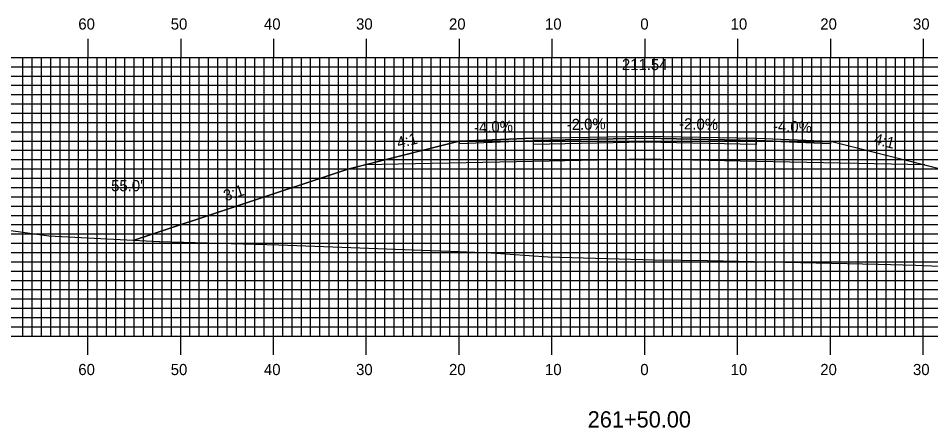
# Model space of a CAD drawing. Extents: x 1806258 to 1806601, y 442591 to 442811.
# Drawn here: x 1806356.2 to 1806454.5, y 442648.8 to 442692.9 of the extents above; entities that cross this region are included whole.
import ezdxf

# ---------------------------------------------------------------- set-up
doc = ezdxf.new("R2010")
doc.units = 0
for name, color, linetype in [('ANNOTATION', 7, 'Continuous'), ('D_Roadway_Centerline', 7, 'Continuous'), ('D_Roadway_Centerline_Text', 7, 'Continuous'), ('D_Roadway_Edge_Shoulder', 7, 'Continuous'), ('D_Roadway_Edge_TW', 7, 'Continuous'), ('D_Roadway_Pavement', 7, 'Continuous'), ('D_Roadway_SlopeLines', 7, 'Continuous'), ('D_Roadway_SubGrade', 7, 'Continuous'), ('D_Text_Standard', 7, 'Continuous'), ('H_V ANNOTATION', 7, 'Continuous'), ('MAJOR', 7, 'Continuous'), ('MINOR', 7, 'Continuous'), ('S_Roadway_Centerline', 7, 'Continuous')]:
    doc.layers.add(name, color=color, linetype=linetype)

msp = doc.modelspace()

# ---------------------------------------------------------------- linework, layer by layer
at = {"layer": 'D_Roadway_Centerline'}
msp.add_lwpolyline([(1806368.738, 442668.982), (1806391.733, 442676.646), (1806393.559, 442677.103), (1806403.733, 442679.646), (1806411.733, 442679.966), (1806423.733, 442680.206), (1806435.733, 442679.966), (1806443.733, 442679.646), (1806453.907, 442677.103), (1806455.733, 442676.646), (1806491.379, 442664.764)], dxfattribs=at)
at = {"layer": 'D_Roadway_Edge_Shoulder'}
for points in [[(1806411.733, 442679.966), (1806403.733, 442679.646), (1806403.733, 442679.396), (1806411.733, 442679.716)], [(1806435.733, 442679.966), (1806443.733, 442679.646), (1806443.733, 442679.396), (1806435.733, 442679.716)]]:
    msp.add_lwpolyline(points, close=True, dxfattribs=at)
at = {"layer": 'D_Roadway_Edge_TW'}
msp.add_lwpolyline([(1806411.733, 442679.716), (1806411.733, 442679.966), (1806423.733, 442680.206), (1806435.733, 442679.966), (1806435.733, 442679.716), (1806423.733, 442679.956)], close=True, dxfattribs=at)
at = {"layer": 'D_Roadway_Pavement'}
msp.add_lwpolyline([(1806411.733, 442679.3), (1806411.733, 442679.716), (1806423.733, 442679.956), (1806435.733, 442679.716), (1806435.733, 442679.3), (1806423.733, 442679.54)], close=True, dxfattribs=at)
at = {"layer": 'D_Roadway_SlopeLines'}
for points in [[(1806403.733, 442679.646), (1806391.733, 442676.646), (1806368.738, 442668.982)], [(1806443.733, 442679.646), (1806455.733, 442676.646), (1806491.379, 442664.764)]]:
    msp.add_lwpolyline(points, dxfattribs=at)
at = {"layer": 'D_Roadway_SubGrade'}
msp.add_lwpolyline([(1806411.733, 442677.466), (1806393.559, 442677.103), (1806403.733, 442679.646), (1806403.733, 442679.396), (1806411.733, 442679.716), (1806423.733, 442679.956), (1806435.733, 442679.716), (1806443.733, 442679.396), (1806443.733, 442679.646), (1806453.907, 442677.103), (1806435.733, 442677.466), (1806423.733, 442677.706)], close=True, dxfattribs=at)
at = {"layer": 'MAJOR'}
for p, q in [((1806363.733, 442690.669), (1806363.733, 442688.665)), ((1806373.733, 442690.669), (1806373.733, 442688.665)), ((1806383.733, 442690.669), (1806383.733, 442688.665)), ((1806393.733, 442690.669), (1806393.733, 442688.665)), ((1806403.733, 442690.669), (1806403.733, 442688.665)), ((1806413.733, 442690.669), (1806413.733, 442688.665)), ((1806423.733, 442690.669), (1806423.733, 442688.665)), ((1806433.733, 442690.669), (1806433.733, 442688.665)), ((1806443.733, 442690.669), (1806443.733, 442688.665)), ((1806453.733, 442690.669), (1806453.733, 442688.665)), ((1806283.733, 442688.665), (1806563.733, 442688.665)), ((1806283.733, 442688.665), (1806563.733, 442688.665)), ((1806363.733, 442658.665), (1806363.733, 442688.665)), ((1806373.733, 442658.665), (1806373.733, 442688.665)), ((1806383.733, 442658.665), (1806383.733, 442688.665)), ((1806393.733, 442658.665), (1806393.733, 442688.665)), ((1806403.733, 442658.665), (1806403.733, 442688.665)), ((1806413.733, 442658.665), (1806413.733, 442688.665)), ((1806423.733, 442658.665), (1806423.733, 442688.665)), ((1806433.733, 442658.665), (1806433.733, 442688.665)), ((1806443.733, 442658.665), (1806443.733, 442688.665)), ((1806453.733, 442658.665), (1806453.733, 442688.665)), ((1806283.733, 442683.665), (1806563.733, 442683.665)), ((1806283.733, 442678.665), (1806563.733, 442678.665)), ((1806283.733, 442673.665), (1806563.733, 442673.665)), ((1806283.733, 442668.665), (1806563.733, 442668.665)), ((1806283.733, 442663.665), (1806563.733, 442663.665)), ((1806283.733, 442658.665), (1806563.733, 442658.665)), ((1806283.733, 442658.665), (1806563.733, 442658.665)), ((1806363.733, 442656.661), (1806363.733, 442658.665)), ((1806373.733, 442656.661), (1806373.733, 442658.665)), ((1806383.733, 442656.661), (1806383.733, 442658.665)), ((1806393.733, 442656.661), (1806393.733, 442658.665)), ((1806403.733, 442656.661), (1806403.733, 442658.665)), ((1806413.733, 442656.661), (1806413.733, 442658.665)), ((1806423.733, 442656.661), (1806423.733, 442658.665)), ((1806433.733, 442656.661), (1806433.733, 442658.665)), ((1806443.733, 442656.661), (1806443.733, 442658.665)), ((1806453.733, 442656.661), (1806453.733, 442658.665))]:
    msp.add_line(p, q, dxfattribs=at)
at = {"layer": 'MINOR'}
for p, q in [((1806356.733, 442658.665), (1806356.733, 442688.665)), ((1806357.733, 442658.665), (1806357.733, 442688.665)), ((1806358.733, 442658.665), (1806358.733, 442688.665)), ((1806359.733, 442658.665), (1806359.733, 442688.665)), ((1806360.733, 442658.665), (1806360.733, 442688.665)), ((1806361.733, 442658.665), (1806361.733, 442688.665)), ((1806362.733, 442658.665), (1806362.733, 442688.665)), ((1806364.733, 442658.665), (1806364.733, 442688.665)), ((1806365.733, 442658.665), (1806365.733, 442688.665)), ((1806366.733, 442658.665), (1806366.733, 442688.665)), ((1806367.733, 442658.665), (1806367.733, 442688.665)), ((1806368.733, 442658.665), (1806368.733, 442688.665)), ((1806369.733, 442658.665), (1806369.733, 442688.665)), ((1806370.733, 442658.665), (1806370.733, 442688.665)), ((1806371.733, 442658.665), (1806371.733, 442688.665)), ((1806372.733, 442658.665), (1806372.733, 442688.665)), ((1806374.733, 442658.665), (1806374.733, 442688.665)), ((1806375.733, 442658.665), (1806375.733, 442688.665)), ((1806376.733, 442658.665), (1806376.733, 442688.665)), ((1806377.733, 442658.665), (1806377.733, 442688.665)), ((1806378.733, 442658.665), (1806378.733, 442688.665)), ((1806379.733, 442658.665), (1806379.733, 442688.665)), ((1806380.733, 442658.665), (1806380.733, 442688.665)), ((1806381.733, 442658.665), (1806381.733, 442688.665)), ((1806382.733, 442658.665), (1806382.733, 442688.665)), ((1806384.733, 442658.665), (1806384.733, 442688.665)), ((1806385.733, 442658.665), (1806385.733, 442688.665)), ((1806386.733, 442658.665), (1806386.733, 442688.665)), ((1806387.733, 442658.665), (1806387.733, 442688.665)), ((1806388.733, 442658.665), (1806388.733, 442688.665)), ((1806389.733, 442658.665), (1806389.733, 442688.665)), ((1806390.733, 442658.665), (1806390.733, 442688.665)), ((1806391.733, 442658.665), (1806391.733, 442688.665)), ((1806392.733, 442658.665), (1806392.733, 442688.665)), ((1806394.733, 442658.665), (1806394.733, 442688.665)), ((1806395.733, 442658.665), (1806395.733, 442688.665)), ((1806396.733, 442658.665), (1806396.733, 442688.665)), ((1806397.733, 442658.665), (1806397.733, 442688.665)), ((1806398.733, 442658.665), (1806398.733, 442688.665)), ((1806399.733, 442658.665), (1806399.733, 442688.665)), ((1806400.733, 442658.665), (1806400.733, 442688.665)), ((1806401.733, 442658.665), (1806401.733, 442688.665)), ((1806402.733, 442658.665), (1806402.733, 442688.665)), ((1806404.733, 442658.665), (1806404.733, 442688.665)), ((1806405.733, 442658.665), (1806405.733, 442688.665)), ((1806406.733, 442658.665), (1806406.733, 442688.665)), ((1806407.733, 442658.665), (1806407.733, 442688.665)), ((1806408.733, 442658.665), (1806408.733, 442688.665)), ((1806409.733, 442658.665), (1806409.733, 442688.665)), ((1806410.733, 442658.665), (1806410.733, 442688.665)), ((1806411.733, 442658.665), (1806411.733, 442688.665)), ((1806412.733, 442658.665), (1806412.733, 442688.665)), ((1806414.733, 442658.665), (1806414.733, 442688.665)), ((1806415.733, 442658.665), (1806415.733, 442688.665)), ((1806416.733, 442658.665), (1806416.733, 442688.665)), ((1806417.733, 442658.665), (1806417.733, 442688.665)), ((1806418.733, 442658.665), (1806418.733, 442688.665)), ((1806419.733, 442658.665), (1806419.733, 442688.665)), ((1806420.733, 442658.665), (1806420.733, 442688.665)), ((1806421.733, 442658.665), (1806421.733, 442688.665)), ((1806422.733, 442658.665), (1806422.733, 442688.665)), ((1806424.733, 442658.665), (1806424.733, 442688.665)), ((1806425.733, 442658.665), (1806425.733, 442688.665)), ((1806426.733, 442658.665), (1806426.733, 442688.665)), ((1806427.733, 442658.665), (1806427.733, 442688.665)), ((1806428.733, 442658.665), (1806428.733, 442688.665)), ((1806429.733, 442658.665), (1806429.733, 442688.665)), ((1806430.733, 442658.665), (1806430.733, 442688.665)), ((1806431.733, 442658.665), (1806431.733, 442688.665)), ((1806432.733, 442658.665), (1806432.733, 442688.665)), ((1806434.733, 442658.665), (1806434.733, 442688.665)), ((1806435.733, 442658.665), (1806435.733, 442688.665)), ((1806436.733, 442658.665), (1806436.733, 442688.665)), ((1806437.733, 442658.665), (1806437.733, 442688.665)), ((1806438.733, 442658.665), (1806438.733, 442688.665)), ((1806439.733, 442658.665), (1806439.733, 442688.665)), ((1806440.733, 442658.665), (1806440.733, 442688.665)), ((1806441.733, 442658.665), (1806441.733, 442688.665)), ((1806442.733, 442658.665), (1806442.733, 442688.665)), ((1806444.733, 442658.665), (1806444.733, 442688.665)), ((1806445.733, 442658.665), (1806445.733, 442688.665)), ((1806446.733, 442658.665), (1806446.733, 442688.665)), ((1806447.733, 442658.665), (1806447.733, 442688.665)), ((1806448.733, 442658.665), (1806448.733, 442688.665)), ((1806449.733, 442658.665), (1806449.733, 442688.665)), ((1806450.733, 442658.665), (1806450.733, 442688.665)), ((1806451.733, 442658.665), (1806451.733, 442688.665)), ((1806452.733, 442658.665), (1806452.733, 442688.665)), ((1806283.733, 442687.665), (1806563.733, 442687.665)), ((1806283.733, 442686.665), (1806563.733, 442686.665)), ((1806283.733, 442685.665), (1806563.733, 442685.665)), ((1806283.733, 442684.665), (1806563.733, 442684.665)), ((1806283.733, 442682.665), (1806563.733, 442682.665)), ((1806283.733, 442681.665), (1806563.733, 442681.665)), ((1806283.733, 442680.665), (1806563.733, 442680.665)), ((1806283.733, 442679.665), (1806563.733, 442679.665)), ((1806283.733, 442677.665), (1806563.733, 442677.665)), ((1806283.733, 442676.665), (1806563.733, 442676.665)), ((1806283.733, 442675.665), (1806563.733, 442675.665)), ((1806283.733, 442674.665), (1806563.733, 442674.665)), ((1806283.733, 442672.665), (1806563.733, 442672.665)), ((1806283.733, 442671.665), (1806563.733, 442671.665)), ((1806283.733, 442670.665), (1806563.733, 442670.665)), ((1806283.733, 442669.665), (1806563.733, 442669.665)), ((1806283.733, 442667.665), (1806563.733, 442667.665)), ((1806283.733, 442666.665), (1806563.733, 442666.665)), ((1806283.733, 442665.665), (1806563.733, 442665.665)), ((1806283.733, 442664.665), (1806563.733, 442664.665)), ((1806283.733, 442662.665), (1806563.733, 442662.665)), ((1806283.733, 442661.665), (1806563.733, 442661.665)), ((1806283.733, 442660.665), (1806563.733, 442660.665)), ((1806283.733, 442659.665), (1806563.733, 442659.665))]:
    msp.add_line(p, q, dxfattribs=at)
at = {"layer": 'S_Roadway_Centerline'}
msp.add_lwpolyline([(1806283.733, 442674.369), (1806285.606, 442674.322), (1806289.498, 442674.217), (1806294.936, 442673.999), (1806308.977, 442673.524), (1806319.797, 442672.814), (1806329.498, 442672.267), (1806346.386, 442671.128), (1806350.558, 442670.726), (1806359.544, 442669.457), (1806371.43, 442668.842), (1806371.443, 442668.841), (1806371.447, 442668.841), (1806384.312, 442668.489), (1806403.663, 442667.786), (1806407.191, 442667.644), (1806413.316, 442667.189), (1806424.781, 442666.864), (1806430.476, 442666.818), (1806448.883, 442666.414), (1806452.93, 442666.309), (1806456.315, 442666.145)], dxfattribs=at)

# ---------------------------------------------------------------- texts
at = {"layer": 'ANNOTATION'}
for s, rotation, p in [('-2.0%', 1.14576, (1806415.339, 442680.839)), ('-2.0%', 358.85424, (1806427.419, 442680.933)), ('-4.0%', 2.29061, (1806405.364, 442680.513)), ('-4.0%', 357.70939, (1806437.524, 442680.696)), ('4:1', 14.03624, (1806397.181, 442678.87)), ('4:1', 345.96376, (1806448.325, 442679.36)), ('3:1', 18.43478, (1806378.574, 442673.168))]:
    msp.add_text(s, height=1.2, rotation=rotation, dxfattribs=at).set_placement(p)
at = {"layer": 'D_Roadway_Centerline'}
for s, p in [('C', (1806423.727, 442680.206)), ('L', (1806423.733, 442680.199))]:
    msp.add_text(s, height=0.0146, dxfattribs=at).set_placement(p)
at = {"layer": 'D_Roadway_Centerline_Text'}
msp.add_text('211.54', height=1.2, dxfattribs=at).set_placement((1806421.271, 442687.299))
at = {"layer": 'D_Text_Standard'}
msp.add_text("55.0'", height=1.2, dxfattribs=at).set_placement((1806366.239, 442674.262))
at = {"layer": 'H_V ANNOTATION'}
for s, height, p in [('60', 1.2, (1806362.705, 442691.665)), ('50', 1.2, (1806372.662, 442691.665)), ('40', 1.2, (1806382.705, 442691.665)), ('30', 1.2, (1806392.63, 442691.665)), ('20', 1.2, (1806402.641, 442691.665)), ('10', 1.2, (1806412.983, 442691.665)), ('0', 1.2, (1806423.251, 442691.665)), ('10', 1.2, (1806432.983, 442691.665)), ('20', 1.2, (1806442.641, 442691.665)), ('30', 1.2, (1806452.63, 442691.665)), ('60', 1.2, (1806362.705, 442654.465)), ('50', 1.2, (1806372.662, 442654.465)), ('40', 1.2, (1806382.705, 442654.465)), ('30', 1.2, (1806392.63, 442654.465)), ('20', 1.2, (1806402.641, 442654.465)), ('10', 1.2, (1806412.983, 442654.465)), ('0', 1.2, (1806423.251, 442654.465)), ('10', 1.2, (1806432.983, 442654.465)), ('20', 1.2, (1806442.641, 442654.465)), ('30', 1.2, (1806452.63, 442654.465)), ('261+50.00', 1.75, (1806417.584, 442648.821))]:
    msp.add_text(s, height=height, dxfattribs=at).set_placement(p)

doc.saveas('drawing.dxf')
